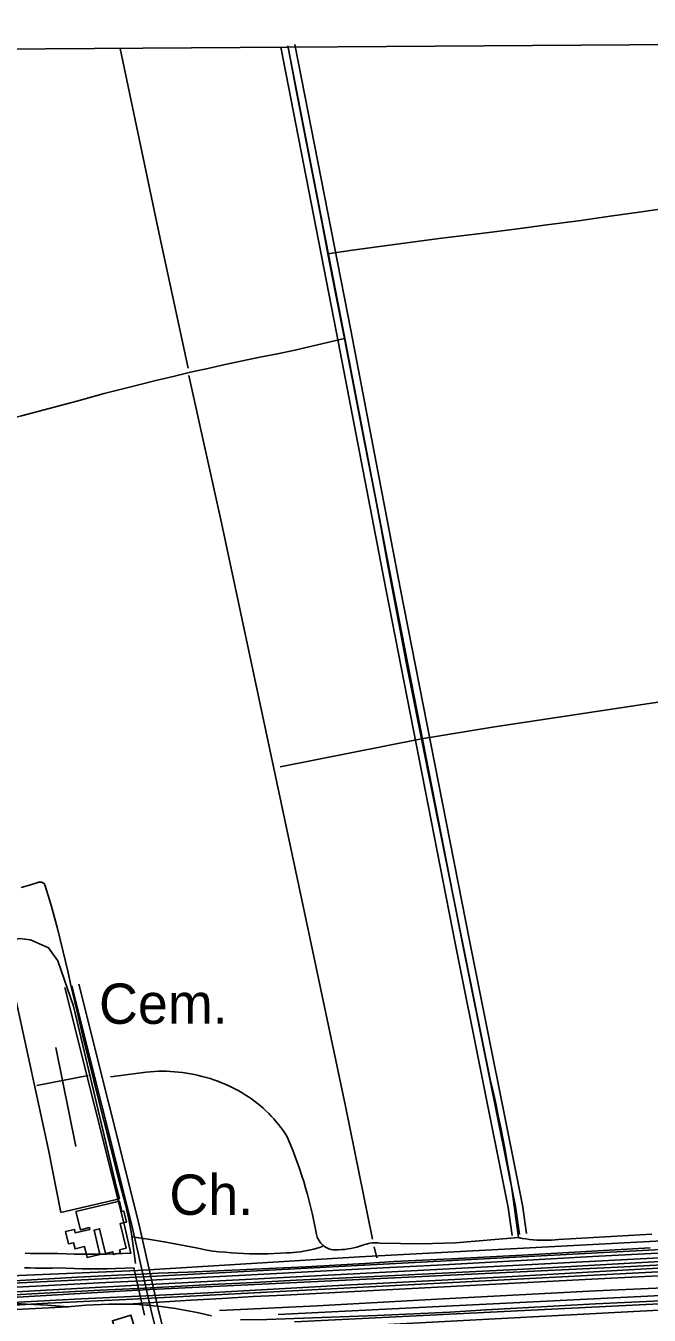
# Model space of a CAD drawing. Extents: x 3508733 to 3546731, y 546897 to 572481.
# Drawn here: x 3515478 to 3516762, y 567889 to 570545 of the extents above; entities that cross this region are included whole.
import ezdxf

# ---------------------------------------------------------------- set-up
doc = ezdxf.new("R2010")
doc.units = 0
for name, color, linetype in [('V-BLDG-OTLN', 7, 'Continuous'), ('V-DTCH-CNTR', 7, 'Continuous'), ('V-GRID-FRAM', 7, 'Continuous'), ('V-RAIL-TRAK', 7, 'Continuous'), ('V-ROAD-CNTR', 7, 'Continuous'), ('V-SITE-OTLN', 7, 'Continuous'), ('V-SITE-OTLN-IDEN', 7, 'Continuous'), ('V-TOPO-SHOR', 7, 'Continuous')]:
    doc.layers.add(name, color=color, linetype=linetype)

msp = doc.modelspace()

# ---------------------------------------------------------------- linework, layer by layer
at = {"layer": 'V-BLDG-OTLN'}
for points in [[(3515581.2, 568103.4), (3515670.5, 568124.6), (3515675.6, 568103.2), (3515679.6, 568104.1), (3515685, 568081.4), (3515672.2, 568078.4), (3515684.3, 568027.5), (3515671.1, 568024.3), (3515672.7, 568017.7), (3515658.4, 568014.2), (3515657, 568020.1), (3515642, 568016.5), (3515629.9, 568067.5), (3515618.5, 568064.8), (3515630.5, 568014.5), (3515604.3, 568008.3), (3515598.9, 568030.8), (3515579.4, 568026.2), (3515576.4, 568038.8), (3515566, 568036.3), (3515559.9, 568061.9), (3515578, 568066.2), (3515579.7, 568058.9), (3515610, 568066.1), (3515609.1, 568070.1), (3515590.2, 568065.6)], [(3515667.8, 567840), (3515706, 567851.7), (3515694.3, 567889.9), (3515656.1, 567878.2)]]:
    msp.add_lwpolyline(points, close=True, dxfattribs=at)
at = {"layer": 'V-DTCH-CNTR'}
for points in [[(3516018.1, 570500.9), (3516034.9, 570412.8), (3516061.4, 570275.3), (3516088.2, 570137.8), (3516100.2, 570075.4), (3516115.1, 569998.1), (3516134, 569900.8), (3516142.2, 569858.5), (3516169.5, 569719), (3516197.1, 569579.4), (3516209.5, 569510.4), (3516222.1, 569441.4), (3516234.9, 569372.4), (3516248, 569303.5), (3516261.4, 569234.7), (3516274.9, 569165.8), (3516292.9, 569076.5), (3516302.7, 569028.3), (3516335.3, 568864.9), (3516368.1, 568701.5), (3516401.1, 568538.1), (3516434.5, 568374.8), (3516440.2, 568350), (3516445.8, 568325.2), (3516451.1, 568300.3), (3516456.2, 568275.4), (3516461.2, 568250.4), (3516465.9, 568225.4), (3516470.3, 568200.3), (3516474.6, 568175.2), (3516478.7, 568150.1), (3516482.5, 568124.9)], [(3516811.4, 570171.3), (3516746.4, 570161.9), (3516681.3, 570152.7), (3516616.2, 570143.7), (3516551, 570134.9), (3516485.9, 570126.4), (3516420.6, 570118.2), (3516374.8, 570112.7), (3516329, 570106.9), (3516283.2, 570101), (3516237.4, 570094.9), (3516191.6, 570088.6), (3516145.9, 570082.1), (3516100.2, 570075.4)], [(3515011.3, 569628.6), (3515068.7, 569642.1), (3515126, 569655.8), (3515183.2, 569669.7), (3515240.4, 569683.7), (3515297.6, 569698), (3515354.7, 569712.5), (3515411.8, 569727.1), (3515468.8, 569741.9), (3515525.8, 569757), (3515582.7, 569772.2), (3515639.5, 569787.6), (3515675, 569796.8), (3515710.4, 569805.7), (3515746, 569814.5), (3515781.6, 569823), (3515817.2, 569831.4), (3515852.9, 569839.5), (3515888.6, 569847.3), (3515924.4, 569855), (3515960.2, 569862.5), (3515996.1, 569869.7), (3516032, 569876.7), (3516134, 569900.8)], [(3518426.6, 569365.4), (3518194.1, 569343.4), (3517851.5, 569304.8), (3517538, 569271), (3517390.6, 569252.3), (3517144.5, 569210.9), (3516820.7, 569158.5), (3516438.9, 569100.3), (3516292.9, 569076.5), (3516001.6, 569018.6)], [(3515703.7, 567996.3), (3515702, 568011.6), (3515700, 568026.8), (3515697.9, 568042.1), (3515695.4, 568057.2), (3515692.8, 568072.4), (3515689.9, 568087.5), (3515686.7, 568102.5), (3515683.4, 568117.5), (3515668.4, 568174.1), (3515653.6, 568230.8), (3515639.1, 568287.6), (3515624.8, 568344.4), (3515610.8, 568401.3), (3515597, 568458.2), (3515583.4, 568515.2), (3515570, 568572.3), (3515565, 568595.1), (3515559.8, 568617.9), (3515554.4, 568640.7), (3515548.7, 568663.4), (3515542.9, 568686), (3515536.8, 568708.6), (3515530.5, 568731.2), (3515524, 568753.6), (3515517.3, 568776.1), (3515516.4, 568777.3), (3515515.4, 568778.5), (3515514.2, 568779.5), (3515512.9, 568780.3), (3515511.5, 568781), (3515510, 568781.4), (3515508.5, 568781.7), (3515506.9, 568781.7), (3515505.4, 568781.5), (3515503.9, 568781.2), (3515502.5, 568780.6), (3515485.4, 568775.3), (3515468.3, 568770.2)], [(3515742.6, 568391.4), (3515734.3, 568390.9), (3515726, 568390.2), (3515652.1, 568380.2)], [(3515993.7, 568288.1), (3515988.7, 568293.9), (3515983.4, 568299.6), (3515978.1, 568305.1), (3515972.5, 568310.5), (3515966.9, 568315.7), (3515961, 568320.7), (3515955.1, 568325.6), (3515949, 568330.4), (3515942.8, 568334.9), (3515936.4, 568339.3), (3515930, 568343.5), (3515923.4, 568347.5), (3515916.7, 568351.4), (3515909.9, 568355), (3515903.1, 568358.5), (3515896.1, 568361.8), (3515888.5, 568365.2), (3515880.8, 568368.4), (3515873.1, 568371.4), (3515865.3, 568374.2), (3515857.4, 568376.8), (3515849.4, 568379.2), (3515841.4, 568381.4), (3515833.3, 568383.4), (3515825.2, 568385.1), (3515817.1, 568386.7), (3515808.9, 568388.1), (3515800.6, 568389.2), (3515792.4, 568390.2), (3515784.1, 568390.9), (3515775.8, 568391.5), (3515767.5, 568391.8), (3515759.2, 568391.9), (3515750.9, 568391.8), (3515742.6, 568391.4)], [(3516492.8, 568049.3), (3516363.2, 568038.3), (3516291.9, 568036.6), (3516207.2, 568038.2), (3516203.2, 568038.6), (3516199.3, 568038.7), (3516195.3, 568038.6), (3516191.3, 568038.3), (3516187.3, 568037.8), (3516183.4, 568037), (3516179.5, 568036.1), (3516175.7, 568034.9), (3516171.9, 568033.5), (3516165.9, 568031.6), (3516159.8, 568029.9), (3516153.6, 568028.4), (3516147.4, 568027.1), (3516141.1, 568026), (3516134.8, 568025.1), (3516128.5, 568024.5), (3516122.1, 568024), (3516115.8, 568023.8), (3516112.9, 568023.9), (3516110, 568024.3), (3516107.2, 568024.8), (3516104.4, 568025.6), (3516101.7, 568026.5), (3516099.1, 568027.7), (3516096.5, 568029), (3516094.1, 568030.5), (3516091.7, 568032.2), (3516089.5, 568034), (3516087.4, 568036), (3516085.5, 568038.1), (3516083.7, 568040.4), (3516082.1, 568042.8), (3516080.6, 568045.3), (3516079.3, 568047.8), (3516078.2, 568050.5), (3516077.4, 568053.2), (3516076.7, 568056), (3516074.1, 568069.8), (3516071.2, 568083.5), (3516068.2, 568097.2), (3516065, 568110.9), (3516061.6, 568124.5), (3516058, 568138), (3516054.2, 568151.5), (3516050.2, 568164.9), (3516046, 568178.3), (3516041.5, 568191.6), (3516036.9, 568204.8), (3516032.1, 568218), (3516027.1, 568231.1), (3516021.9, 568244.1), (3516016.5, 568257.1), (3516012.3, 568263.5), (3516007.9, 568269.9), (3516003.4, 568276.1), (3515998.6, 568282.1), (3515993.7, 568288.1)], [(3516482.5, 568124.9), (3516486.1, 568099.8), (3516489.6, 568074.5), (3516492.8, 568049.3)], [(3515696.5, 568050.6), (3515729.9, 568046.2), (3515763.1, 568040.8), (3515785.1, 568036.8), (3515807.1, 568032.6), (3515829, 568028.1), (3515850.9, 568023.4), (3515863.4, 568021.7), (3515876, 568020.3), (3515888.6, 568019), (3515901.2, 568017.9), (3515913.8, 568017.1), (3515926.4, 568016.4), (3515939.1, 568016), (3515951.8, 568015.8), (3515964.4, 568015.8), (3515977.1, 568016), (3515989.7, 568016.4), (3516002.4, 568017), (3516015, 568017.9), (3516022.1, 568018.1), (3516029.2, 568018.6), (3516036.3, 568019.2), (3516043.4, 568020.1), (3516050.4, 568021.2), (3516057.5, 568022.5), (3516064.4, 568024), (3516071.3, 568025.8), (3516078.2, 568027.7), (3516085, 568029.8), (3516091.7, 568032.2)], [(3516492.8, 568049.3), (3516500.2, 568047.8), (3516507.6, 568046.6), (3516515.1, 568045.6), (3516522.6, 568044.9), (3516530.2, 568044.3), (3516537.7, 568044), (3516545.3, 568043.9), (3516552.8, 568044), (3516560.4, 568044.3), (3516567.9, 568044.9), (3516575.4, 568045.7), (3516671.5, 568051), (3516767.7, 568056.1)]]:
    msp.add_lwpolyline(points, dxfattribs=at)
at = {"layer": 'V-GRID-FRAM'}
msp.add_lwpolyline([(3512800, 570478.9), (3544431.3, 570695.1), (3544563.5, 552512.4), (3512916.4, 552296.1), (3512800, 570478.9)], dxfattribs=at)
at = {"layer": 'V-RAIL-TRAK'}
for points in [[(3514632.1, 567871.2), (3515067.9, 567895), (3515329.1, 567908.8), (3515365.6, 567910.8), (3515437.5, 567914.7), (3515592.1, 567923.2), (3515724.8, 567929.6), (3515852.8, 567935.8), (3516134, 567951.3), (3516467.7, 567968.8), (3516780, 567986.7), (3517019.1, 567997.7), (3517288, 568013.3), (3517327.5, 568015.4), (3517335.5, 568015.8), (3517351.5, 568017.7), (3517367.6, 568019.7), (3517383.6, 568021.9), (3517399.7, 568024.3), (3517415.6, 568027), (3517431.6, 568029.8), (3517447.5, 568032.8), (3517463.4, 568035.9)], [(3516763.6, 568028), (3516631.9, 568020.6), (3516500.2, 568013.5), (3516368.4, 568006.6), (3516236.7, 567999.8), (3516175.9, 567996.2), (3516115.2, 567992.7), (3516054.4, 567989.4), (3515993.7, 567986.3), (3515932.9, 567983.4), (3515872.1, 567980.7), (3515811.3, 567978.1), (3515750.5, 567975.8), (3515715.7, 567974.2), (3515667.5, 567971.8), (3515584.4, 567967.6), (3515501.3, 567963), (3515418.3, 567958.3)], [(3515432.5, 567946.1), (3515537.6, 567951.5), (3515642.8, 567956.8), (3515718.3, 567960.6), (3515748, 567962.1), (3515903.3, 567970.5), (3516058.6, 567978.9), (3516213.9, 567987.2), (3516325.1, 567992.8), (3516436.2, 567998.7), (3516547.4, 568004.7), (3516658.5, 568011), (3516806.2, 568018.5)], [(3515688.8, 567912.3), (3515729.6, 567914.9), (3515753.2, 567916.4), (3515817.5, 567920.4), (3515882, 567924.1), (3515946.4, 567927.7), (3516010.8, 567931), (3516075.2, 567934.2), (3516220.6, 567941.5), (3516365.9, 567949), (3516511.2, 567956.6), (3516656.5, 567964.3), (3516835.2, 567973.6), (3517013.8, 567983.1), (3517192.4, 567992.8), (3517211.8, 567995.4), (3517231.2, 567998.1), (3517250.5, 568001.1), (3517269.8, 568004.4), (3517289.1, 568007.8), (3517308.3, 568011.5), (3517327.5, 568015.4)], [(3516797.8, 568000.7), (3516698.2, 567995.1), (3516600.6, 567989.6), (3516503, 567984.4), (3516405.3, 567979.4), (3516307.7, 567974.6), (3516210, 567970), (3516122.5, 567965.9), (3516035, 567961.6), (3515947.5, 567957.2), (3515860.1, 567952.7), (3515772.6, 567948), (3515722.1, 567945.4), (3515631.5, 567940.8), (3515490.4, 567933.3), (3515349.4, 567925.4)], [(3515860.4, 567888.5), (3515845.6, 567891.8), (3515830.8, 567894.9), (3515815.8, 567897.8), (3515800.9, 567900.5), (3515785.9, 567903), (3515770.8, 567905.2), (3515755.8, 567907.2), (3515740.7, 567909), (3515731.4, 567909.9), (3515725.6, 567910.5), (3515710.4, 567911.8), (3515695, 567912.2), (3515688.8, 567912.3), (3515679.5, 567912.4), (3515664, 567912.4), (3515648.6, 567912.1), (3515633.1, 567911.6), (3515617.6, 567910.9), (3515601.7, 567909.9), (3515586.8, 567908.8), (3515571.4, 567907.4), (3515565.1, 567907), (3515431, 567900)], [(3515437.5, 567914.7), (3515480, 567912.4), (3515522.6, 567909.9), (3515565.1, 567907)], [(3516726.2, 567916.5), (3516651.2, 567912.8), (3516576.3, 567908.9), (3516501.3, 567904.7), (3516426.4, 567900.4), (3516351.5, 567895.8), (3516276.1, 567892.2), (3516200.6, 567888.9), (3516125.2, 567885.9), (3516049.8, 567883.1), (3515974.3, 567880.6), (3515920.4, 567879.9)], [(3516801.1, 567919.9), (3516726.2, 567916.5)]]:
    msp.add_lwpolyline(points, dxfattribs=at)
at = {"layer": 'V-ROAD-CNTR'}
for points in [[(3516494.6, 568055.8), (3516486.4, 568113.6), (3516377, 568658.3), (3516234.5, 569384.7), (3516132.4, 569915.3), (3516017.6, 570504)], [(3516509.5, 568057.9), (3516501.2, 568116.1), (3516391.7, 568661.2), (3516249.3, 569387.6), (3516147.1, 569918.2), (3516032.3, 570506.9)], [(3516479.8, 568053.6), (3516471.6, 568111), (3516362.3, 568655.4), (3516219.8, 569381.9), (3516117.6, 569912.5), (3516002.9, 570501.2)], [(3515737.3, 567893), (3515695.6, 568077.6), (3515572.7, 568567.8)], [(3515751.9, 567896.3), (3515710.2, 568081), (3515587.2, 568571.5)], [(3515694, 568016.6), (3515681, 568074.1), (3515558.1, 568564.2)], [(3521093.6, 568241.2), (3520798.8, 568217.3), (3520420.1, 568201.5), (3520267.2, 568189.5), (3519841.4, 568172.7), (3519690.1, 568163.7), (3519221.2, 568133.3), (3518627.7, 568097), (3518514.4, 568086.1), (3518236, 568067.9), (3518068, 568075.1), (3517535.9, 568046.7), (3517450.7, 568038.9), (3517163.5, 567998.8), (3515683.7, 567921.8), (3515524.1, 567914.4), (3515291.1, 567900.9), (3514216.2, 567847.3), (3513979.5, 567857.1)], [(3518191.9, 568122.3), (3517571.8, 568084), (3516866.3, 568047.1), (3516165.4, 568009.4), (3515708.4, 567981.5), (3515316.1, 567964.8), (3514386.4, 567914.5), (3513892.8, 567898.4), (3513315.9, 567858.5), (3512894, 567835.8)], [(3518542.8, 568118.1), (3518357.5, 568109.2), (3517909.1, 568085.5), (3517484.7, 568062.2), (3516968.2, 568034.6), (3515719.5, 567968.5), (3514984.8, 567932.9), (3513660.5, 567861.9), (3512913.6, 567818.7)], [(3517498.1, 568043.3), (3516927.4, 568015.4), (3515733.3, 567952.6), (3515145, 567920.4), (3513967, 567863.4), (3513481.3, 567836.2), (3512928.2, 567802.8)], [(3517319.4, 568020.6), (3516697, 567988.2), (3515719.5, 567941.5), (3515389.1, 567922.2)], [(3515476.6, 568017.4), (3515487.7, 568016.8), (3515498.8, 568016.5), (3515509.9, 568016.3), (3515521, 568016.3), (3515532, 568016.5), (3515543.8, 568016.9), (3515561.2, 568016), (3515578, 568015.5), (3515594.7, 568015.1), (3515611.4, 568014.9), (3515628.1, 568015), (3515644.8, 568015.3), (3515661.5, 568015.8), (3515693.9, 568017.1)], [(3515474.9, 567987.4), (3515486.5, 567986.8), (3515498.1, 567986.5), (3515509.6, 567986.3), (3515521.2, 567986.3), (3515532.8, 567986.5), (3515543.6, 567986.8), (3515560, 567986.1), (3515577.1, 567985.5), (3515594.2, 567985.1), (3515611.3, 567984.9), (3515628.4, 567985), (3515645.5, 567985.3), (3515662.6, 567985.8), (3515700.8, 567987.4)], [(3515722.6, 567889.7), (3515700.6, 567987.3)], [(3515997.4, 567891), (3518114, 567996.3)], [(3518017.2, 567976.4), (3517270.5, 567936.9), (3516031.4, 567875.9)], [(3516145.9, 567866), (3516872.9, 567905), (3517857.4, 567953)], [(3516119.9, 566404), (3516029.5, 566732.6), (3515737.3, 567893)], [(3516134.4, 566407.9), (3516044, 566736.4), (3515751.8, 567896.6)]]:
    msp.add_lwpolyline(points, dxfattribs=at)
at = {"layer": 'V-SITE-OTLN'}
for p, q in [((3515580.7, 568236.7), (3515539.9, 568440.9)), ((3515606.3, 568383.4), (3515500.7, 568362.3))]:
    msp.add_line(p, q, dxfattribs=at)
msp.add_lwpolyline([(3515549.7, 568100.7), (3515524.5, 568229.8), (3515434.1, 568647.6), (3515443.1, 568660.7), (3515464.4, 568665.4), (3515487.8, 568662.6), (3515524.3, 568646), (3515544.1, 568619.1), (3515576.2, 568526.2), (3515664.7, 568152.3), (3515670.5, 568129.2)], close=True, dxfattribs=at)
at = {"layer": 'V-TOPO-SHOR'}
msp.add_line((3516201.2, 568008), (3516195.5, 568030.3), dxfattribs=at)
for points in [[(3515812, 569840.3), (3515750.3, 570126.4), (3515672.3, 570498.5)], [(3516191.9, 568045.8), (3516136.3, 568320.1), (3516056, 568699.8), (3515965.7, 569125), (3515881.2, 569521.5), (3515813.8, 569824.7)], [(3515876.8, 567899), (3516077.9, 567908.5), (3516337.7, 567923.3), (3516651.5, 567939.5), (3516962.8, 567953.3), (3517313.5, 567972.2), (3517535, 567995.6), (3517547.1, 567996.2), (3517548.7, 567999.5), (3517549.9, 568006.2), (3517549.6, 568015.7), (3517549.7, 568027.3)]]:
    msp.add_lwpolyline(points, dxfattribs=at)

# ---------------------------------------------------------------- texts
at = {"layer": 'V-SITE-OTLN-IDEN'}
for s, p in [('Cem.', (3515628.6, 568489.6)), ('Ch.', (3515773.5, 568096.2))]:
    msp.add_text(s, height=83, dxfattribs=at).set_placement(p)

doc.saveas('drawing.dxf')
